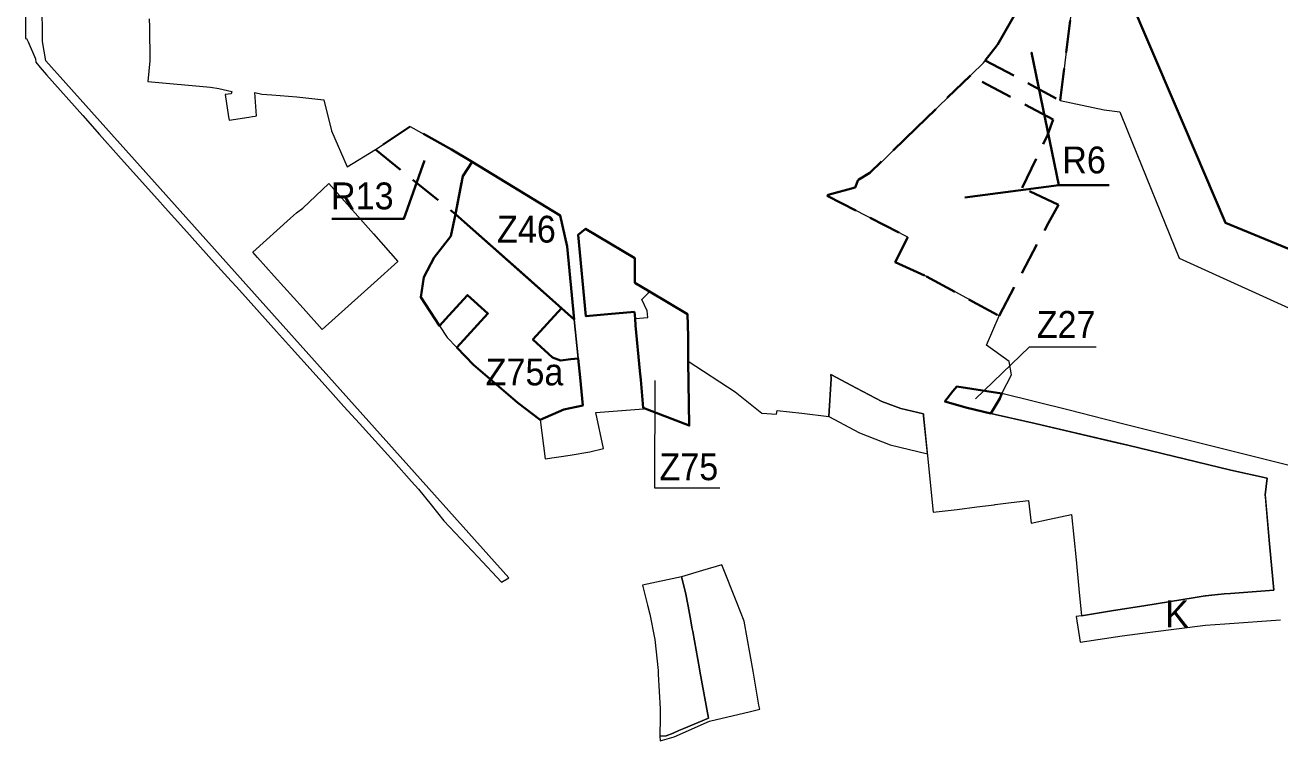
# Model space of a CAD drawing. Extents: x -650276 to -642489, y -1074425 to -1066658.
# Drawn here: x -650276 to -649154, y -1070494 to -1069854 of the extents above; entities that cross this region are included whole.
import ezdxf

# ---------------------------------------------------------------- set-up
doc = ezdxf.new("R2010")
doc.units = 0
doc.header["$LTSCALE"] = 9.6
doc.linetypes.add('MEDIUM_DASHED', pattern=[4.5, 3, -1.5])
for name, color, linetype, lineweight in [('1', 7, 'Continuous', 13), ('43', 7, 'Continuous', 13), ('45', 7, 'Continuous', 40), ('46', 7, 'Continuous', 13), ('47', 7, 'Continuous', 13), ('61', 7, 'MEDIUM_DASHED', 40), ('62', 7, 'Continuous', 35)]:
    doc.layers.add(name, color=color, linetype=linetype, lineweight=lineweight)

msp = doc.modelspace()

# ---------------------------------------------------------------- linework, layer by layer
at = {"layer": '1'}
for points in [[(-650165.14, -1069847.93), (-650165.06, -1069855.42), (-650164.75, -1069885.61), (-650166.37, -1069903.94), (-650110.46, -1069909.09), (-650102.82, -1069910.23), (-650091.19, -1069912.91), (-650091.77, -1069914.85), (-650097.23, -1069915.55), (-650094.12, -1069935.66), (-650093.66, -1069938.66), (-650076.17, -1069935.89), (-650072.66, -1069935.33), (-650070.36, -1069934.96), (-650069.07, -1069934.76), (-650070.55, -1069913.65), (-650064.44, -1069915.23), (-650055.55, -1069915.97), (-650033.04, -1069917.65), (-650008.9, -1069920.42), (-650002.19, -1069947.99), (-649988.08, -1069980.36), (-649962.67, -1069964.78), (-649931.76, -1069944.31), (-649896.43, -1069963.81), (-649876.31, -1069975.93), (-649858.12, -1069986.96), (-649853.14, -1069989.98), (-649797.45, -1070023.77), (-649791.31, -1070051.51), (-649784.87, -1070116.76), (-649779.75, -1070168.69), (-649777.29, -1070193.57), (-649794.37, -1070197.2), (-649815.33, -1070206.63), (-649810.95, -1070241.37), (-649788.61, -1070237.95), (-649770.85, -1070235.23), (-649758.85, -1070232.1), (-649765.78, -1070200.07), (-649746.16, -1070198.54), (-649723.08, -1070196.73), (-649723.17, -1070195.81), (-649724.92, -1070176.78), (-649725.49, -1070170.64), (-649726.22, -1070162.75), (-649730, -1070122.01), (-649730.57, -1070115.76), (-649719.24, -1070114.87), (-649719.69, -1070108.94), (-649724.36, -1070099.03), (-649718.71, -1070093.35)], [(-649683.57, -1070112.05), (-649682.98, -1070132.1), (-649683.09, -1070148.44), (-649683.12, -1070154.14), (-649641.12, -1070181.47), (-649617.13, -1070200.55), (-649604.09, -1070201.32), (-649603.52, -1070198.23), (-649581.42, -1070200.66), (-649557.21, -1070203.53), (-649555.15, -1070169.51), (-649555.44, -1070165.91), (-649532.57, -1070178.08), (-649509.72, -1070190.24), (-649492.67, -1070196.34), (-649472.6, -1070201.15), (-649472.43, -1070202.9), (-649463.78, -1070289.2), (-649442.39, -1070286.54), (-649424.9, -1070284.37), (-649409.29, -1070282.43), (-649408.24, -1070282.3), (-649394.21, -1070280.56), (-649378.58, -1070278.61), (-649376.08, -1070298.82), (-649359.77, -1070295.29), (-649340.12, -1070291.04), (-649335.99, -1070331.84), (-649333.64, -1070357.71), (-649331.3, -1070381.69), (-649304.18, -1070377.35), (-649273.57, -1070372.44), (-649231.39, -1070365.69), (-649220.47, -1070363.94), (-649219.97, -1070363.89), (-649203.4, -1070362.23), (-649197.91, -1070361.8), (-649159.19, -1070358.82), (-649162.91, -1070317.47), (-649166.68, -1070275.52), (-649166.86, -1070273.48), (-649164.91, -1070258.55), (-649197.55, -1070251.65), (-649289.83, -1070229.16), (-649372.69, -1070209.74), (-649408.24, -1070201.62), (-649412.2, -1070200.71), (-649433.3, -1070195.89), (-649453.27, -1070190.02), (-649446.19, -1070180.76), (-649442.63, -1070176.69), (-649402.29, -1070182.92), (-649393.69, -1070166.16), (-649396.01, -1070154.28), (-649416.25, -1070139.65), (-649404.76, -1070113.41), (-649443.63, -1070092.44), (-649469.85, -1070078.3), (-649473.14, -1070076.8), (-649497.95, -1070065.49), (-649486.5, -1070043.26), (-649558.56, -1070006.13), (-649557.92, -1070005.19), (-649533.61, -1069998.6), (-649530.31, -1069991.5), (-649520.6, -1069985.72), (-649511.39, -1069977.25), (-649481, -1069947.32), (-649479.08, -1069945.53), (-649440.39, -1069908.03), (-649418.94, -1069887.36), (-649406.53, -1069871.59), (-649391.86, -1069846.18)], [(-649889.87, -1070141.83), (-649862.22, -1070111.54), (-649880.42, -1070094.87), (-649894.094, -1070109.853), (-649897.03, -1070113.07), (-649905.51, -1070122.35)], [(-649718.71, -1070093.35), (-649717.72, -1070091.61), (-649704.42, -1070099.48), (-649683.57, -1070112.05)], [(-649796.4, -1070106.56), (-649821.97, -1070134.58), (-649804.29, -1070150.68)], [(-649784.87, -1070116.76), (-649791.58, -1070110.83), (-649796.4, -1070106.56)], [(-649804.29, -1070150.68), (-649797.33, -1070153.41), (-649787.92, -1070152.23), (-649781.436, -1070151.591), (-649784.87, -1070116.76)], [(-649905.51, -1070122.35), (-649898.55, -1070132.9), (-649889.87, -1070141.83)], [(-649469.02, -1070236.92), (-649472.43, -1070202.9), (-649472.6, -1070201.15), (-649492.67, -1070196.34), (-649509.72, -1070190.24), (-649532.57, -1070178.08), (-649555.44, -1070165.91), (-649555.15, -1070169.51), (-649557.21, -1070203.53), (-649529.75, -1070218.06)], [(-649529.75, -1070218.06), (-649502.36, -1070228.94), (-649469.02, -1070236.92)], [(-649708.37, -1070489.38), (-649708.08, -1070493.61), (-649695.44, -1070490.03), (-649663.84, -1070475.94), (-649627.41, -1070467.18), (-649618.85, -1070465.12), (-649619.72, -1070461.73), (-649624.97, -1070431.24), (-649633, -1070386.46), (-649639.56, -1070370), (-649653.03, -1070336.2), (-649670.28, -1070341.35), (-649689.02, -1070346.94)], [(-649691.28, -1070484.4), (-649686.94, -1070482.59), (-649664.82, -1070473.32), (-649672.49, -1070431.16), (-649672.83, -1070429.29), (-649678.92, -1070395.81), (-649679.37, -1070393.37), (-649681.29, -1070382.89), (-649683.08, -1070373.11), (-649685.31, -1070360.88), (-649689.02, -1070346.94), (-649723.88, -1070354.28), (-649719.45, -1070372.18), (-649717.42, -1070380.41), (-649712.85, -1070403.03), (-649709.94, -1070430.67)], [(-649689.02, -1070346.94), (-649685.31, -1070360.88), (-649683.08, -1070373.11)], [(-649683.08, -1070373.11), (-649681.29, -1070382.89), (-649679.37, -1070393.37), (-649678.92, -1070395.81)], [(-649678.92, -1070395.81), (-649672.83, -1070429.29), (-649672.49, -1070431.16), (-649664.82, -1070473.32)], [(-649709.94, -1070430.67), (-649709.77, -1070433.9), (-649708.12, -1070464.95), (-649708.2, -1070472.48), (-649708.37, -1070489.38), (-649702.69, -1070488.94), (-649696.59, -1070486.63), (-649691.28, -1070484.4)], [(-649664.82, -1070473.32), (-649686.94, -1070482.59), (-649691.28, -1070484.4)], [(-649691.28, -1070484.4), (-649696.59, -1070486.63), (-649702.69, -1070488.94), (-649708.37, -1070489.38)]]:
    msp.add_lwpolyline(points, dxfattribs=at)
msp.add_lwpolyline([(-650004.5, -1069995.2), (-649964.64, -1070040.29), (-649942.76, -1070065.03), (-649963.86, -1070083.92), (-650010.44, -1070125.63), (-650027.58, -1070106.62), (-650053.4, -1070077.97), (-650068.42, -1070061.31), (-650072.57, -1070056.71), (-650038.78, -1070026.24), (-650033.55, -1070021.52), (-650033.55, -1070021.52), (-650027.71, -1070017.13)], close=True, dxfattribs=at)
at = {"layer": '45'}
for points in [[(-649312.03, -1069773.33), (-649246.81, -1069926.27), (-649246.81, -1069926.27), (-649239.635, -1069943.094), (-649202.375, -1070030.469), (-649202.375, -1070030.469), (-649085.737, -1070078.201)], [(-649730.837, -1070084.028), (-649730.6, -1070061.98), (-649774.73, -1070035.58), (-649781.53, -1070041.2), (-649774.45, -1070113.92), (-649754.82, -1070111.89), (-649731.12, -1070109.96)], [(-649730.837, -1070084.028), (-649730.6, -1070061.98), (-649774.73, -1070035.58), (-649781.53, -1070041.2), (-649774.45, -1070113.92), (-649754.82, -1070111.89), (-649731.12, -1070109.96)], [(-649731.12, -1070109.96), (-649730.57, -1070115.76), (-649730, -1070122.01), (-649726.22, -1070162.75), (-649725.49, -1070170.64), (-649723.17, -1070195.81), (-649682.04, -1070211.58), (-649683.12, -1070154.14), (-649682.98, -1070132.1), (-649683.57, -1070112.05), (-649717.72, -1070091.61), (-649730.837, -1070084.028)], [(-649731.12, -1070109.96), (-649730.57, -1070115.76), (-649730, -1070122.01), (-649726.22, -1070162.75), (-649725.49, -1070170.64), (-649723.17, -1070195.81), (-649682.04, -1070211.58), (-649683.12, -1070154.14), (-649682.98, -1070132.1), (-649683.57, -1070112.05), (-649717.72, -1070091.61), (-649730.837, -1070084.028)]]:
    msp.add_lwpolyline(points, dxfattribs=at)
for points in [[(-649891.21, -1070022.68), (-649832.007, -1070074.751), (-649784.87, -1070116.76), (-649791.31, -1070051.51), (-649797.45, -1070023.77), (-649876.31, -1069975.93), (-649884.59, -1069988.57)], [(-649891.21, -1070022.68), (-649832.007, -1070074.751), (-649784.87, -1070116.76), (-649791.31, -1070051.51), (-649797.45, -1070023.77), (-649876.31, -1069975.93), (-649884.59, -1069988.57)], [(-649891.21, -1070022.68), (-649895.45, -1070042.15), (-649910.34, -1070061.29), (-649919.55, -1070079.01), (-649922.3, -1070096.9), (-649905.51, -1070122.35), (-649897.03, -1070113.07), (-649880.42, -1070094.87), (-649862.22, -1070111.54), (-649889.87, -1070141.83), (-649874.94, -1070157.19), (-649835.28, -1070191.27), (-649815.33, -1070206.63), (-649794.37, -1070197.2), (-649777.29, -1070193.57), (-649779.75, -1070168.69), (-649781.436, -1070151.591), (-649787.92, -1070152.23), (-649797.33, -1070153.41), (-649804.29, -1070150.68), (-649821.97, -1070134.58), (-649796.4, -1070106.56)], [(-649442.63, -1070176.69), (-649402.29, -1070182.92), (-649404.2, -1070187.43), (-649412.2, -1070200.71), (-649433.3, -1070195.89), (-649453.27, -1070190.02), (-649446.19, -1070180.76)]]:
    msp.add_lwpolyline(points, close=True, dxfattribs=at)
at = {"layer": '46'}
msp.add_line((-649377.965, -1070141.64), (-649426.071, -1070187.689), dxfattribs=at)
for points in [[(-649318.08, -1070141.64), (-649318.08, -1070141.64), (-649377.965, -1070141.64), (-649377.965, -1070141.64)], [(-649654.738, -1070267.746), (-649712.819, -1070267.746), (-649712.819, -1070267.746), (-649712.586, -1070171.248)]]:
    msp.add_lwpolyline(points, dxfattribs=at)
at = {"layer": '47'}
for points in [[(-649538.49, -1069541.54), (-649527.84, -1069552.16), (-649517.81, -1069563.27), (-649507.23, -1069573.85), (-649474.46, -1069613.59), (-649415.12, -1069685.26), (-649401.77, -1069701.47), (-649392.85, -1069713.53), (-649385.25, -1069726.48), (-649379.49, -1069740.04), (-649376.01, -1069754.58), (-649372.2, -1069772.58), (-649370.94, -1069787.45), (-649372.56, -1069802.33), (-649372.56, -1069802.33), (-649338, -1069822), (-649350.222, -1069920.873), (-649310.738, -1069929.342), (-649296.851, -1069931.092)], [(-649202.375, -1070030.469), (-649239.635, -1069943.094), (-649246.81, -1069926.27), (-649246.81, -1069926.27), (-649312.03, -1069773.33), (-649364.44, -1069650.55), (-649379.32, -1069615.71)], [(-650260.665, -1069868.303), (-650260.748, -1069867.327), (-650261.204, -1069797.969), (-650254.411, -1069764.006), (-650255.21, -1069733.253), (-650255.716, -1069731.162), (-650259.97, -1069732.29), (-650264.91, -1069735.69), (-650270.059, -1069739.232)], [(-650270.059, -1069739.232), (-650269.449, -1069762.714), (-650276.214, -1069796.532), (-650275.76, -1069865.474), (-650274.95, -1069865.62)], [(-650274.95, -1069865.62), (-650273.61, -1069868.62), (-650266.89, -1069883.7)], [(-650266.89, -1069883.7), (-650266.68, -1069886.78), (-650262.64, -1069891.57), (-650257.16, -1069898.07), (-650224.71, -1069934.41), (-650209.51, -1069951.43), (-650192.51, -1069970.47), (-650174.3, -1069990.86), (-650157.87, -1070009.26), (-650151.03, -1070016.84), (-650134.26, -1070035.45), (-650106.76, -1070065.96), (-650091.89, -1070082.46), (-650087.18, -1070087.68), (-650076.72, -1070099.29), (-650051.33, -1070127.45), (-650037.78, -1070142.48), (-650018.41, -1070163.97), (-650005.3, -1070178.51), (-649990.95, -1070194.43), (-649977.05, -1070209.85), (-649946.39, -1070243.87), (-649930.46, -1070261.54), (-649924.15, -1070268.55), (-649913.03, -1070282.44), (-649901.59, -1070296.73), (-649871.28, -1070329.01), (-649850.04, -1070351.64), (-649843.513, -1070347.685), (-650257.713, -1069885.547), (-650260.665, -1069868.303)], [(-649296.851, -1069931.092), (-649289.95, -1069948.146), (-649243.846, -1070062.071), (-649126.437, -1070115.217), (-649126.437, -1070115.217), (-649098.101, -1070125.688), (-649085.737, -1070078.201), (-649202.375, -1070030.469)], [(-649130.712, -1070250.935), (-649160.748, -1070243.413), (-649220.52, -1070228.443), (-649288.379, -1070211.449), (-649310.998, -1070205.784), (-649342.149, -1070197.982), (-649402.29, -1070182.92), (-649404.2, -1070187.43), (-649412.2, -1070200.71), (-649408.24, -1070201.62), (-649391.184, -1070205.516), (-649372.69, -1070209.74), (-649335.914, -1070218.359), (-649299.227, -1070226.958), (-649289.83, -1070229.16), (-649197.55, -1070251.65), (-649164.91, -1070258.55), (-649166.86, -1070273.48), (-649162.91, -1070317.47), (-649159.19, -1070358.82), (-649197.91, -1070361.8), (-649203.4, -1070362.23), (-649220.47, -1070363.94), (-649231.39, -1070365.69), (-649273.57, -1070372.44), (-649304.18, -1070377.35), (-649331.3, -1070381.69), (-649335.79, -1070382.41), (-649332.2, -1070405.42), (-649294.79, -1070399.65), (-649269.769, -1070396.502), (-649220.16, -1070390.26), (-649202.969, -1070388.965), (-649153.11, -1070385.21)]]:
    msp.add_lwpolyline(points, dxfattribs=at)
at = {"layer": '61'}
for points in [[(-649372.56, -1069802.33), (-649379.19, -1069820.24), (-649391.86, -1069846.18), (-649406.53, -1069871.59), (-649417.234, -1069885.193), (-649350.222, -1069920.873), (-649338, -1069822)], [(-649430.515, -1069898.514), (-649479.08, -1069945.53), (-649520.6, -1069985.72), (-649530.31, -1069991.5), (-649530.99, -1069991.9), (-649533.61, -1069998.6), (-649557.92, -1070005.19), (-649558.56, -1070006.13), (-649486.5, -1070043.26), (-649497.95, -1070065.49), (-649469.85, -1070078.3), (-649404.76, -1070113.41), (-649360.74, -1070030.35), (-649351.66, -1070014.26), (-649384.249, -1069998.959), (-649361.46, -1069951.93), (-649356.458, -1069937.945)], [(-649931.76, -1069944.31), (-649962.859, -1069964.896), (-649891.21, -1070022.68), (-649884.59, -1069988.57), (-649876.31, -1069975.93), (-649894.68, -1069964.78)]]:
    msp.add_lwpolyline(points, close=True, dxfattribs=at)
at = {"layer": '62'}
for points in [[(-649306.343, -1069996.537), (-649351.328, -1069996.537), (-649375.864, -1069878.046), (-649351.328, -1069996.537), (-649435.663, -1070007.798)], [(-650001.823, -1070026.616), (-649937.373, -1070026.616), (-649918.861, -1069974.471)]]:
    msp.add_lwpolyline(points, dxfattribs=at)
at = {"layer": '62', "lineweight": 13}
msp.add_lwpolyline([(-650001.823, -1070026.616), (-649937.373, -1070026.616), (-649918.861, -1069974.471)], dxfattribs=at)

# ---------------------------------------------------------------- texts
at = {"layer": '43'}
msp.add_text('K', height=24, dxfattribs=at).set_placement((-649256.486, -1070392.051))
at = {"layer": '46', "width": 0.95}
for s, p in [('Z46', (-649853.994, -1070048.002)), ('Z46', (-649853.994, -1070048.002)), ('Z27', (-649371.182, -1070133.176)), ('Z75a', (-649864.164, -1070175.692)), ('Z75', (-649708.673, -1070260.465))]:
    msp.add_text(s, height=24, dxfattribs=at).set_placement(p)
at = {"layer": '62', "width": 0.95}
for s, p in [('R6', (-649348.349, -1069986.108)), ('R13', (-650002.521, -1070018.261)), ('R13', (-650002.521, -1070018.261))]:
    msp.add_text(s, height=24, dxfattribs=at).set_placement(p)

doc.saveas('drawing.dxf')
